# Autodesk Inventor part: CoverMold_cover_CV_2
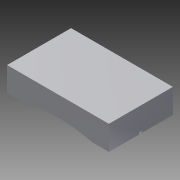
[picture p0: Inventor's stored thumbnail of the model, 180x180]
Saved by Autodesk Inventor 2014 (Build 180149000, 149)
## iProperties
Created: 2009-12
Part Number: CoverMold_cover_CV_2
Document SubType Name: Modeling
Designer: gaom
Density: 1 g/cm^3
Material: Generic
Appearance: Default
Author: gaom
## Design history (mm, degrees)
node "CoverMold_cover_CV_Base"
feature "Solid1::CoverMold_cover_CV_Base"
tag "TaggingFeature1"
body "Solid1"
